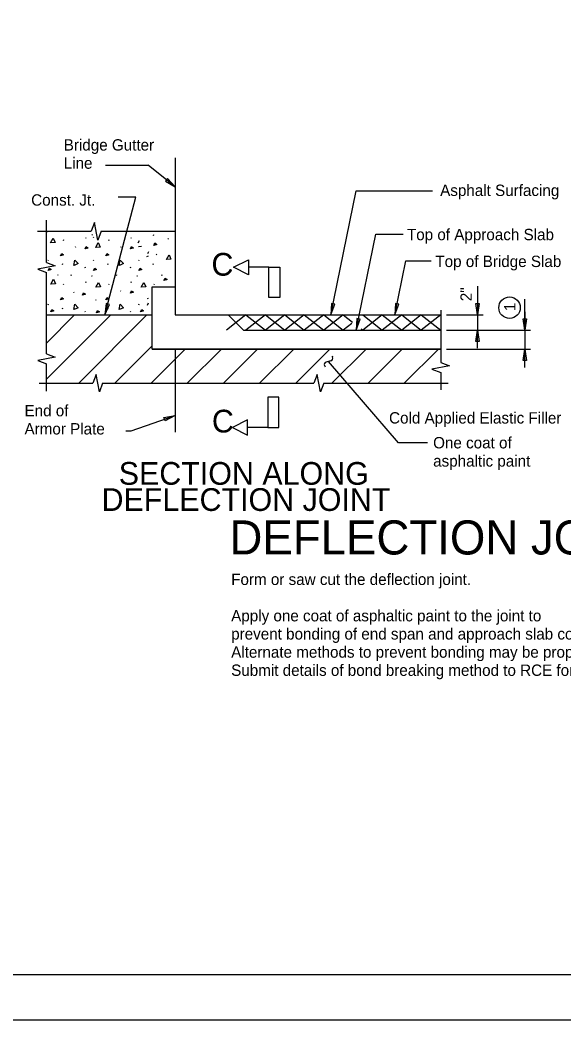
# Model space of a CAD drawing. Extents: x 2799.7 to 2896, y 515.2 to 573.9.
# Drawn here: x 2818.07 to 2834.02, y 515.22 to 544.56 of the extents above; entities that cross this region are included whole.
import ezdxf

# ---------------------------------------------------------------- set-up
doc = ezdxf.new("R2010")
doc.units = 0
for name, color, linetype in [('BR_AUTO DIMENSION', 7, 'Continuous'), ('BR_BORDER LINES', 7, 'Continuous'), ('BR_CONCRETE', 7, 'Continuous'), ('BR_DETAILS', 7, 'Continuous'), ('BR_STRUCTURAL STEEL', 7, 'Continuous'), ('BR_TABLE LINES', 7, 'Continuous'), ('BR_TEXT', 7, 'Continuous'), ('Level 31', 7, 'Continuous')]:
    doc.layers.add(name, color=color, linetype=linetype)

msp = doc.modelspace()

# ---------------------------------------------------------------- linework, layer by layer
at = {"layer": 'BR_AUTO DIMENSION'}
for p, q in [((2822.622, 540.513), (2822.622, 537.193)), ((2820.577, 540.302), (2821.823, 540.302)), ((2822.622, 539.66), (2821.823, 540.302)), ((2827.183, 535.904), (2827.923, 539.544)), ((2827.923, 539.544), (2830.164, 539.544)), ((2820.559, 535.904), (2821.466, 539.359)), ((2821.466, 539.359), (2820.946, 539.359)), ((2827.928, 535.46), (2828.5, 538.275)), ((2828.5, 538.275), (2829.302, 538.275)), ((2829.061, 535.904), (2829.382, 537.488)), ((2829.382, 537.488), (2830.126, 537.488)), ((2831.484, 536.744), (2831.484, 535.904)), ((2831.484, 536.437), (2831.484, 535.904)), ((2832.871, 535.46), (2832.871, 536.37)), ((2832.871, 535.993), (2832.871, 535.46)), ((2830.573, 535.904), (2831.651, 535.904)), ((2831.484, 535.904), (2831.484, 535.46)), ((2830.573, 535.46), (2833.037, 535.46)), ((2830.573, 535.46), (2831.651, 535.46)), ((2831.484, 534.926), (2831.484, 535.46)), ((2832.871, 535.46), (2832.871, 534.904)), ((2830.573, 534.904), (2833.037, 534.904)), ((2832.871, 534.358), (2832.871, 534.904)), ((2832.871, 534.371), (2832.871, 534.904)), ((2827.177, 534.558), (2827.046, 534.521)), ((2829.171, 532.15), (2827.112, 534.539)), ((2827.219, 534.702), (2827.233, 534.671)), ((2826.999, 534.42), (2827.016, 534.378)), ((2821.331, 532.504), (2822.622, 532.956)), ((2821.173, 532.504), (2821.331, 532.504)), ((2830.022, 532.15), (2829.171, 532.15))]:
    msp.add_line(p, q, dxfattribs=at)
for points in [[(2822.331, 539.83), (2822.622, 539.66), (2822.393, 539.908)], [(2820.592, 536.24), (2820.559, 535.904), (2820.689, 536.215)], [(2827.201, 536.241), (2827.183, 535.904), (2827.299, 536.221)], [(2829.078, 536.241), (2829.061, 535.904), (2829.176, 536.221)], [(2831.534, 536.237), (2831.484, 535.904), (2831.434, 536.237)], [(2827.945, 535.796), (2827.928, 535.46), (2828.043, 535.776)], [(2832.921, 535.793), (2832.871, 535.46), (2832.821, 535.793)], [(2831.434, 535.126), (2831.484, 535.46), (2831.534, 535.126)], [(2832.821, 534.571), (2832.871, 534.904), (2832.921, 534.571)], [(2822.291, 532.893), (2822.622, 532.956), (2822.324, 532.799)]]:
    msp.add_lwpolyline(points, close=True, dxfattribs=at)
msp.add_circle((2832.423, 536.117), 0.314, dxfattribs=at)
for centre, radius, start, end in [((2827.059, 534.454), 0.0684, 101.4621, 209.7477), ((2827.165, 534.634), 0.077, 279.0173, 28.8161)]:
    msp.add_arc(centre, radius, start, end, dxfattribs=at)
at = {"layer": 'BR_BORDER LINES'}
msp.add_line((2804.582, 516.556), (2894.359, 516.556), dxfattribs=at)
at = {"layer": 'BR_CONCRETE'}
for p, q in [((2821.945, 536.728), (2822.622, 536.728)), ((2818.844, 535.904), (2821.945, 535.904)), ((2822.622, 535.904), (2830.406, 535.904)), ((2821.945, 534.904), (2830.406, 534.904))]:
    msp.add_line(p, q, dxfattribs=at)
msp.add_lwpolyline([(2822.622, 538.359), (2822.622, 536.728), (2822.622, 535.904)], dxfattribs=at)
at = {"layer": 'BR_DETAILS'}
for p, q in [((2818.586, 538.359), (2820.157, 538.359)), ((2818.844, 538.353), (2818.855, 538.336)), ((2820.446, 538.359), (2822.622, 538.359)), ((2819.341, 538.09), (2819.352, 538.115)), ((2819.998, 538.153), (2820.009, 538.178)), ((2820.179, 538.261), (2820.19, 538.244)), ((2820.213, 538.193), (2820.224, 538.176)), ((2820.67, 538.09), (2820.681, 538.115)), ((2821.328, 538.153), (2821.339, 538.178)), ((2821.529, 538.015), (2821.571, 538.093)), ((2821.986, 538.237), (2821.997, 538.262)), ((2822.408, 538.124), (2822.419, 538.149)), ((2819.688, 537.912), (2819.699, 537.895)), ((2821.017, 537.912), (2821.028, 537.895)), ((2821.636, 537.91), (2821.547, 537.902)), ((2821.819, 537.706), (2821.845, 537.761)), ((2822.066, 537.666), (2822.077, 537.691)), ((2818.891, 537.498), (2818.902, 537.523)), ((2819.313, 537.385), (2819.324, 537.41)), ((2820.22, 537.498), (2820.231, 537.523)), ((2820.642, 537.385), (2820.653, 537.41)), ((2821.55, 537.498), (2821.561, 537.523)), ((2821.83, 537.626), (2821.776, 537.609)), ((2821.972, 537.385), (2821.983, 537.41)), ((2819.973, 537.315), (2819.975, 537.29)), ((2821.302, 537.315), (2821.305, 537.29)), ((2819.167, 537.091), (2819.178, 537.074)), ((2819.341, 536.793), (2819.352, 536.818)), ((2819.565, 537.063), (2819.576, 537.088)), ((2819.998, 536.857), (2820.009, 536.882)), ((2820.162, 537.063), (2820.173, 537.046)), ((2820.173, 537.056), (2820.184, 537.04)), ((2820.67, 536.793), (2820.681, 536.818)), ((2820.895, 537.063), (2820.906, 537.088)), ((2821.328, 536.857), (2821.339, 536.882)), ((2821.491, 537.063), (2821.503, 537.046)), ((2821.503, 537.056), (2821.514, 537.04)), ((2821.999, 536.793), (2822.01, 536.818)), ((2822.224, 537.063), (2822.235, 537.088)), ((2819.639, 536.579), (2819.65, 536.562)), ((2821.017, 536.616), (2821.028, 536.599)), ((2818.891, 536.202), (2818.902, 536.227)), ((2820.288, 536.335), (2820.299, 536.36)), ((2821.55, 536.202), (2821.561, 536.227)), ((2821.831, 536.385), (2821.802, 536.376)), ((2821.807, 536.196), (2821.836, 536.255)), ((2819.313, 536.088), (2819.324, 536.113)), ((2819.973, 536.019), (2819.975, 535.994)), ((2820.642, 536.088), (2820.653, 536.113)), ((2821.302, 536.019), (2821.305, 535.994)), ((2830.406, 536.042), (2830.406, 534.507)), ((2820.73, 535.904), (2818.844, 534.018)), ((2819.67, 535.904), (2818.844, 535.078)), ((2821.791, 535.904), (2819.791, 533.904)), ((2821.945, 534.998), (2820.852, 533.904)), ((2822.912, 534.904), (2821.912, 533.904)), ((2823.973, 534.904), (2822.973, 533.904)), ((2825.034, 534.904), (2824.034, 533.904)), ((2826.094, 534.904), (2825.094, 533.904)), ((2827.155, 534.904), (2826.155, 533.904)), ((2828.216, 534.904), (2827.216, 533.904)), ((2829.277, 534.904), (2828.277, 533.904)), ((2830.337, 534.904), (2829.337, 533.904)), ((2830.406, 534.218), (2830.406, 533.705)), ((2818.632, 533.904), (2820.202, 533.904)), ((2820.492, 533.904), (2826.688, 533.904)), ((2826.977, 533.904), (2830.626, 533.904))]:
    msp.add_line(p, q, dxfattribs=at)
for points in [[(2818.844, 537.439), (2818.844, 538.682)], [(2820.446, 538.359), (2820.35, 538.102), (2820.253, 538.616), (2820.157, 538.359)], [(2818.966, 538.015), (2819.041, 538.156), (2819.099, 538.026), (2818.969, 538.015)], [(2820.29, 537.885), (2820.365, 538.027), (2820.423, 537.896), (2820.293, 537.885)], [(2821.992, 537.946), (2822.025, 538.015), (2822.08, 537.974), (2821.992, 537.946)], [(2819.258, 537.641), (2819.291, 537.711), (2819.347, 537.669), (2819.258, 537.641)], [(2819.979, 537.84), (2820.012, 537.909), (2820.068, 537.868), (2819.979, 537.84)], [(2820.587, 537.641), (2820.621, 537.711), (2820.676, 537.669), (2820.587, 537.641)], [(2821.308, 537.84), (2821.342, 537.909), (2821.397, 537.868), (2821.308, 537.84)], [(2818.844, 537.439), (2819.101, 537.342), (2818.587, 537.246), (2818.844, 537.15)], [(2819.65, 537.356), (2819.672, 537.515), (2819.772, 537.412), (2819.653, 537.357)], [(2820.98, 537.356), (2821.002, 537.515), (2821.101, 537.412), (2820.982, 537.357)], [(2822.363, 537.527), (2822.438, 537.669), (2822.496, 537.538), (2822.366, 537.527)], [(2818.844, 534.76), (2818.844, 537.15)], [(2818.897, 537.207), (2818.93, 537.276), (2818.985, 537.235), (2818.897, 537.207)], [(2820.226, 537.207), (2820.259, 537.276), (2820.315, 537.235), (2820.226, 537.207)], [(2821.555, 537.207), (2821.589, 537.276), (2821.644, 537.235), (2821.555, 537.207)], [(2818.972, 536.808), (2819.046, 536.95), (2819.105, 536.82), (2818.974, 536.808)], [(2820.295, 536.718), (2820.37, 536.86), (2820.429, 536.729), (2820.298, 536.718)], [(2821.625, 536.718), (2821.7, 536.86), (2821.758, 536.729), (2821.627, 536.718)], [(2822.291, 536.913), (2822.325, 536.982), (2822.38, 536.941), (2822.291, 536.913)], [(2819.9, 536.483), (2819.933, 536.552), (2819.988, 536.51), (2819.9, 536.483)], [(2821.308, 536.543), (2821.342, 536.613), (2821.397, 536.571), (2821.308, 536.543)], [(2819.258, 536.345), (2819.291, 536.414), (2819.347, 536.373), (2819.258, 536.345)], [(2820.587, 536.345), (2820.621, 536.414), (2820.676, 536.373), (2820.587, 536.345)], [(2818.972, 535.995), (2819.005, 536.064), (2819.06, 536.023), (2818.972, 535.995)], [(2819.65, 536.06), (2819.672, 536.218), (2819.772, 536.116), (2819.653, 536.061)], [(2820.307, 535.966), (2820.34, 536.035), (2820.396, 535.994), (2820.307, 535.966)], [(2820.98, 536.06), (2821.002, 536.218), (2821.101, 536.116), (2820.982, 536.061)], [(2821.605, 535.993), (2821.638, 536.062), (2821.694, 536.021), (2821.605, 535.993)], [(2818.844, 534.76), (2819.101, 534.663), (2818.587, 534.567), (2818.844, 534.471)], [(2818.844, 533.664), (2818.844, 534.471)], [(2830.406, 534.507), (2830.664, 534.41), (2830.149, 534.314), (2830.406, 534.218)], [(2820.492, 533.904), (2820.395, 533.647), (2820.299, 534.161), (2820.202, 533.904)], [(2826.977, 533.904), (2826.881, 533.647), (2826.784, 534.161), (2826.688, 533.904)]]:
    msp.add_lwpolyline(points, dxfattribs=at)
at = {"layer": 'BR_STRUCTURAL STEEL'}
msp.add_line((2822.622, 534.904), (2822.622, 532.47), dxfattribs=at)
at = {"layer": 'BR_TABLE LINES'}
for p, q in [((2825.365, 537.303), (2824.773, 537.303)), ((2824.692, 535.904), (2824.12, 535.46)), ((2824.692, 535.904), (2825.263, 535.46)), ((2825.263, 535.904), (2824.692, 535.46)), ((2825.835, 535.904), (2825.263, 535.46)), ((2825.263, 535.904), (2825.835, 535.46)), ((2825.835, 535.904), (2826.406, 535.46)), ((2826.406, 535.904), (2825.835, 535.46)), ((2826.978, 535.904), (2826.406, 535.46)), ((2826.406, 535.904), (2826.978, 535.46)), ((2826.978, 535.904), (2827.549, 535.46)), ((2827.549, 535.904), (2826.978, 535.46)), ((2827.549, 535.904), (2827.819, 535.694)), ((2827.797, 535.652), (2827.549, 535.46)), ((2828.121, 535.904), (2828.692, 535.46)), ((2828.692, 535.904), (2828.121, 535.46)), ((2828.121, 535.904), (2828.121, 535.904)), ((2829.264, 535.904), (2828.692, 535.46)), ((2828.692, 535.904), (2829.264, 535.46)), ((2829.264, 535.904), (2829.835, 535.46)), ((2829.835, 535.904), (2829.264, 535.46)), ((2830.406, 535.904), (2829.835, 535.46)), ((2829.835, 535.904), (2830.406, 535.46)), ((2828.068, 535.5), (2828.121, 535.46)), ((2825.332, 532.6), (2824.739, 532.6))]:
    msp.add_line(p, q, dxfattribs=at)
for points in [[(2824.773, 537.081), (2824.328, 537.303), (2824.773, 537.525)], [(2825.691, 536.414), (2825.365, 536.414), (2825.365, 537.303), (2825.691, 537.303)], [(2821.945, 536.728), (2822.622, 536.728), (2822.622, 535.904), (2824.177, 535.904), (2824.622, 535.46), (2830.406, 535.46), (2830.406, 534.904), (2821.945, 534.904)], [(2825.658, 533.489), (2825.332, 533.489), (2825.332, 532.6), (2825.658, 532.6)], [(2824.739, 532.823), (2824.295, 532.6), (2824.739, 532.378)]]:
    msp.add_lwpolyline(points, close=True, dxfattribs=at)
at = {"layer": 'Level 31'}
msp.add_lwpolyline([(2799.693, 573.89), (2799.693, 515.223), (2895.694, 515.223), (2895.694, 573.89)], dxfattribs=at)

# ---------------------------------------------------------------- texts
at = {"layer": 'BR_AUTO DIMENSION'}
msp.add_text('2"', height=0.3334, rotation=90, dxfattribs=at).set_placement((2831.317, 536.307))
at = {"layer": 'BR_TEXT'}
for s, height, p in [('Bridge Gutter', 0.33332, (2819.351, 540.726)), ('Line', 0.3333, (2819.351, 540.193)), ('Asphalt Surfacing', 0.33332, (2830.389, 539.394)), ('Const. Jt.', 0.3333, (2818.397, 539.11)), ('Top of Approach Slab', 0.33332, (2829.415, 538.097)), ('C', 0.667, (2823.682, 537.056)), ('Top of Bridge Slab', 0.33332, (2830.249, 537.31)), ('End of', 0.3333, (2818.201, 532.932)), ('C', 0.667, (2823.696, 532.456)), ('Cold Applied Elastic Filler', 0.33332, (2828.891, 532.719)), ('Armor Plate', 0.33332, (2818.201, 532.398)), ('One coat of', 0.33332, (2830.183, 531.99)), ('SECTION ALONG', 0.66673, (2820.964, 530.923)), ('asphaltic paint', 0.33332, (2830.183, 531.456)), ('DEFLECTION JOINT', 0.66673, (2820.46, 530.156)), ('DEFLECTION JOINT DETAIL', 1.00005, (2824.21, 528.878)), ('Form or saw cut the deflection joint.', 0.33332, (2824.261, 527.983)), ('Apply one coat of asphaltic paint to the joint to', 0.33332, (2824.261, 526.916)), ('prevent bonding of end span and approach slab concrete.', 0.33332, (2824.261, 526.383)), ('Alternate methods to prevent bonding may be proposed.', 0.33332, (2824.261, 525.85)), ('Submit details of bond breaking method to RCE for approval.', 0.33332, (2824.261, 525.317))]:
    msp.add_text(s, height=height, dxfattribs=at).set_placement(p)
msp.add_text('1', height=0.333, rotation=90, dxfattribs=at).set_placement((2832.598, 536.02))

doc.saveas('drawing.dxf')
